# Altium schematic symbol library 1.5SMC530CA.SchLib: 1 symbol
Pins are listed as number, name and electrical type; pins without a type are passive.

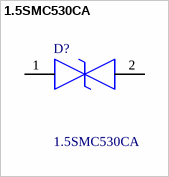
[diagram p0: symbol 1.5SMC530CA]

## 1.5SMC530CA
designator D?
725V Clamp 2.1A Ipp Tvs Diode Surface Mount DO-214AB (SMCJ); Manufacturer_Name: LITTELFUSE; Geometry.Height: 2.62mm
footprint DIONM7969X262N
pins: 1, 2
